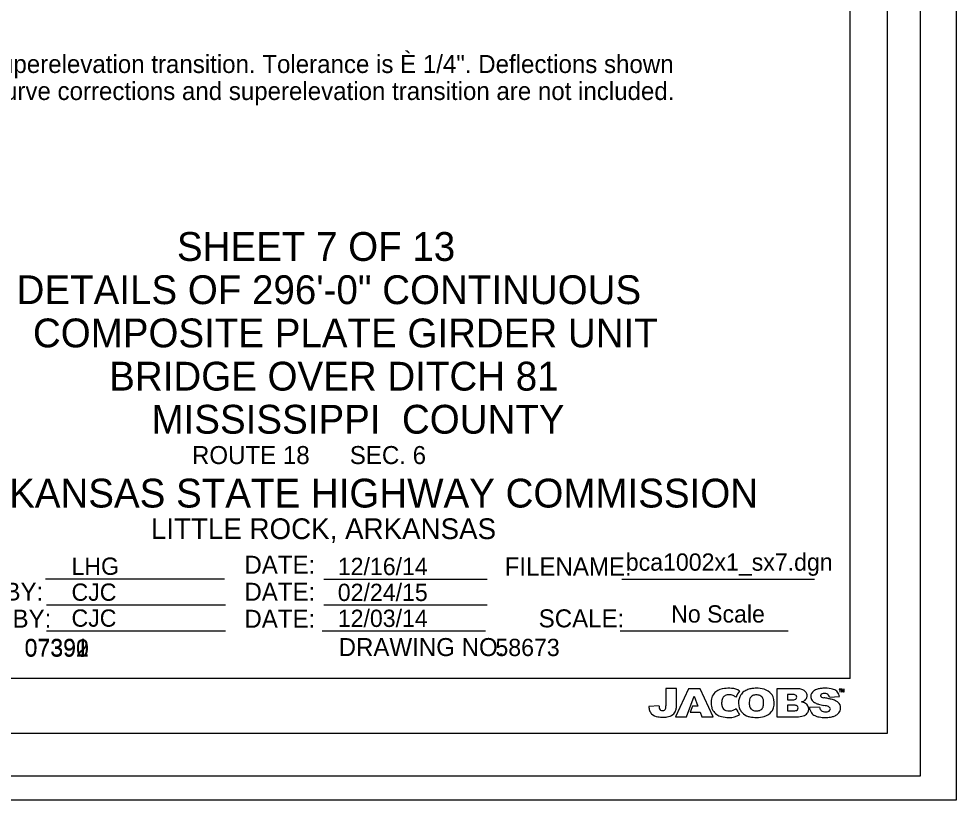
# Model space of a CAD drawing. Extents: x 208.5 to 250.5, y 328.7 to 350.7.
# Drawn here: x 236.52 to 243.03, y 328.74 to 334.16 of the extents above; entities that cross this region are included whole.
import ezdxf

# ---------------------------------------------------------------- set-up
doc = ezdxf.new("R2010")
doc.units = 0
for name, color, linetype in [('border', 7, 'Continuous'), ('Border 2660-Hwy18 - Level 62', 7, 'Continuous'), ('Border 2660-Hwy18 - Level 63', 7, 'Continuous'), ('Border 2660-Hwy18 - Text', 7, 'Continuous'), ('Border 2660-Hwy18 - Title Text', 7, 'Continuous'), ('Bridge No BLFR', 7, 'Continuous'), ('Bridge No BLO', 7, 'Continuous'), ('Bridge No Ditch 81', 7, 'Continuous'), ('Level 40', 7, 'Continuous'), ('Level 62 PDF', 7, 'Continuous'), ('Text', 7, 'Continuous'), ('Title Text', 7, 'Continuous')]:
    doc.layers.add(name, color=color, linetype=linetype)

msp = doc.modelspace()

# ---------------------------------------------------------------- linework, layer by layer
at = {"layer": 'border'}
for p, q in [((242.2907, 329.584), (242.2907, 350.1292)), ((236.7035, 330.2752), (237.9467, 330.2752)), ((238.6367, 330.2741), (239.7707, 330.2741)), ((240.7067, 330.2741), (242.0428, 330.2741)), ((236.7107, 330.0952), (237.9539, 330.0952)), ((238.6367, 330.0941), (239.7707, 330.0941)), ((236.7107, 329.9152), (237.9539, 329.9152)), ((238.6259, 329.9141), (239.7599, 329.9141)), ((240.6943, 329.9141), (241.8599, 329.9141)), ((242.2907, 329.584), (210.2795, 329.584))]:
    msp.add_line(p, q, dxfattribs=at)
for points in [[(241.0855, 329.4044), (241.0855, 329.5145), (241.0114, 329.5145), (241.0114, 329.3938)], [(241.2083, 329.4619), (241.2344, 329.3914), (241.1956, 329.3914), (241.1796, 329.3491), (241.2498, 329.3491), (241.2616, 329.3167), (241.339, 329.3167), (241.2495, 329.5127), (241.1687, 329.5127), (241.0789, 329.3167), (241.1545, 329.3167), (241.2083, 329.4619)], [(241.9247, 329.5127), (241.7825, 329.5127), (241.7825, 329.3167)], [(241.8896, 329.4731), (241.8569, 329.4731), (241.8569, 329.4359)], [(242.2293, 329.5103), (242.2142, 329.5103), (242.2142, 329.5085), (242.2202, 329.5085), (242.2202, 329.4915), (242.2229, 329.4915), (242.2229, 329.5085), (242.2293, 329.5085), (242.2293, 329.5103)], [(242.2338, 329.5073), (242.2338, 329.5073), (242.2399, 329.4915), (242.2417, 329.4915), (242.2477, 329.5073), (242.2477, 329.5073), (242.2477, 329.4915), (242.2502, 329.4915), (242.2502, 329.5103), (242.2468, 329.5103), (242.2408, 329.4946), (242.2347, 329.5103), (242.2314, 329.5103), (242.2314, 329.4915), (242.2338, 329.4915), (242.2338, 329.5073)], [(241.8569, 329.4359), (241.8914, 329.4359)], [(242.1476, 329.4543), (242.2175, 329.4577)], [(240.9639, 329.3929), (240.8931, 329.3893)], [(241.8944, 329.3984), (241.8569, 329.3984), (241.8569, 329.3587)], [(241.8569, 329.3587), (241.895, 329.3587)], [(242.0786, 329.3851), (242.0085, 329.3814)], [(241.7825, 329.3167), (241.9101, 329.3167)]]:
    msp.add_lwpolyline(points, dxfattribs=at)
for centre, radius, start, end in [((241.4075, 329.4273), 0.0809, 126.85134, 155.24445), ((241.4272, 329.401), 0.1137, 94.78534, 126.85134), ((241.448, 329.1527), 0.3629, 86.90301, 94.78534), ((241.4615, 329.4026), 0.1126, 56.9246, 86.90301), ((241.7478, 329.3374), 0.2758, 144.63502, 154.88444), ((241.5953, 329.43), 0.0755, 123.8806, 148.62486), ((241.6324, 329.3747), 0.1421, 111.71043, 123.8806), ((241.6203, 329.4051), 0.1094, 96.53712, 111.71043), ((241.6516, 329.1325), 0.3838, 91.9058, 96.53711), ((241.6458, 329.3501), 0.1661, 73.44767, 92.42532), ((241.6612, 329.4019), 0.1121, 41.1934, 73.44767), ((241.702, 329.4375), 0.0579, 18.69658, 41.1934), ((241.888, 329.3379), 0.1352, 86.2098, 89.3498), ((241.9247, 329.409), 0.1036, 72.18854, 90.1477), ((241.938, 329.4503), 0.0603, 61.48438, 72.18854), ((241.9398, 329.4537), 0.0564, 34.7868, 61.48438), ((241.9603, 329.4679), 0.0315, 16.94547, 34.7868), ((241.9469, 329.4638), 0.0455, 347.09493, 16.94546), ((242.0649, 329.4576), 0.0476, 124.07995, 177.64848), ((242.0961, 329.4116), 0.1032, 108.28083, 124.07995), ((242.0891, 329.4326), 0.0811, 99.81734, 108.28082), ((242.1166, 329.2736), 0.2425, 93.402, 99.81734), ((242.0951, 329.4664), 0.00877, 130.78548, 146.47062), ((242.1061, 329.4537), 0.0256, 97.30547, 130.78548), ((242.1173, 329.2621), 0.2539, 80.65488, 93.40199), ((242.1117, 329.4104), 0.0692, 81.32121, 97.30546), ((242.1167, 329.4434), 0.0359, 57.47403, 81.32121), ((242.1251, 329.4566), 0.0202, 37.19775, 57.47403), ((242.144, 329.4242), 0.0897, 57.59056, 80.65488), ((242.1656, 329.4582), 0.0494, 39.0736, 57.59056), ((242.1564, 329.4508), 0.0612, 6.43854, 39.0736), ((241.4781, 329.4185), 0.1532, 178.6811, 194.39118), ((241.4237, 329.4198), 0.0987, 155.24445, 178.6811), ((241.5022, 329.4122), 0.1037, 161.28337, 178.67021), ((241.4839, 329.4126), 0.0855, 178.67021, 195.85307), ((241.427, 329.4377), 0.0243, 134.3139, 161.28337), ((241.4489, 329.4152), 0.0556, 110.76549, 134.31389), ((241.4479, 329.4177), 0.0529, 91.50728, 110.76549), ((241.4496, 329.3548), 0.1159, 82.6359, 91.50728), ((241.4581, 329.4209), 0.0493, 65.55483, 82.6359), ((241.4294, 329.3577), 0.1187, 54.60016, 65.55482), ((241.6165, 329.4171), 0.1003, 148.62486, 181.28594), ((241.6685, 329.4183), 0.1523, 181.28594, 193.19556), ((241.6817, 329.4145), 0.0917, 160.86113, 181.29811), ((241.6851, 329.4146), 0.0951, 181.29811, 197.94918), ((241.6222, 329.4351), 0.0287, 136.11771, 160.86113), ((241.6389, 329.4191), 0.0518, 117.7176, 136.11771), ((241.6326, 329.4311), 0.0382, 100.21085, 117.7176), ((241.6416, 329.3807), 0.0895, 90.96753, 100.21085), ((241.6406, 329.4079), 0.0622, 67.07702, 90.42176), ((241.6498, 329.4297), 0.0386, 24.62738, 67.07702), ((241.634, 329.4224), 0.056, 2.74416, 24.62738), ((241.5992, 329.4134), 0.091, 342.40029, 0.08449), ((241.4408, 329.4132), 0.2494, 0.08449, 2.74416), ((241.6333, 329.4143), 0.1305, 344.57078, 18.69658), ((241.8913, 329.4992), 0.0633, 270.03631, 284.14376), ((241.8936, 329.4214), 0.0514, 74.87225, 86.2098), ((241.902, 329.4569), 0.0196, 284.14376, 307.88655), ((241.9019, 329.4522), 0.0196, 40.24248, 74.87225), ((241.9049, 329.4531), 0.0149, 307.88655, 341.46246), ((241.9086, 329.4578), 0.0108, 21.96041, 40.24248), ((241.9006, 329.4546), 0.0195, 341.46246, 21.96041), ((241.9344, 329.4939), 0.0753, 284.67851, 296.84115), ((241.9374, 329.3305), 0.092, 61.0815, 79.92424), ((241.9472, 329.4687), 0.0471, 296.84115, 329.81819), ((241.963, 329.3769), 0.039, 44.97734, 61.0815), ((241.9613, 329.4605), 0.0307, 329.81819, 347.09492), ((242.0589, 329.4579), 0.0416, 177.64848, 218.85347), ((242.0706, 329.4673), 0.0566, 218.85347, 233.65492), ((242.0842, 329.4858), 0.0797, 233.65493, 244.76888), ((242.1169, 329.5551), 0.1563, 244.76888, 253.47301), ((242.0936, 329.4644), 0.00815, 165.3108, 208.28871), ((242.1011, 329.4625), 0.016, 146.47062, 165.31079), ((242.1008, 329.4695), 0.0169, 211.74165, 226.63389), ((242.0991, 329.4677), 0.0145, 226.63389, 245.14291), ((242.1161, 329.5044), 0.0549, 245.14291, 260.98065), ((242.0323, 328.9767), 0.4794, 77.5139, 80.98065), ((241.7085, 327.5143), 1.9772, 76.80348, 77.5139), ((242.1133, 329.4476), 0.0351, 11.00509, 37.19775), ((242.1226, 329.2805), 0.1631, 65.69981, 76.80348), ((242.1578, 329.3584), 0.0776, 51.35648, 65.6998), ((242.1736, 329.3782), 0.0523, 36.51625, 51.35648), ((242.1766, 329.3804), 0.0486, 345.16113, 36.51625), ((241.0151, 329.3989), 0.1226, 184.56975, 198.10689), ((240.9486, 329.3771), 0.0527, 198.1069, 225.97986), ((241.0243, 329.3909), 0.0602, 178.25555, 191.49609), ((240.9924, 329.3844), 0.0277, 191.49609, 218.75114), ((240.9836, 329.3773), 0.0164, 218.75114, 257.48803), ((240.9875, 329.395), 0.0345, 257.48804, 275.78339), ((240.9884, 329.3862), 0.0257, 275.78339, 301.69258), ((240.9955, 329.3748), 0.0122, 301.69258, 325.41713), ((240.9821, 329.384), 0.0285, 325.41713, 349.15753), ((240.9323, 329.3936), 0.0792, 349.15753, 360), ((241.0249, 329.3809), 0.0585, 305.86462, 338.78432), ((241.0303, 329.3788), 0.0527, 338.78433, 350.09512), ((240.5413, 329.4642), 0.5492, 350.09512, 351.37058), ((240.9619, 329.4004), 0.1237, 351.37058, 1.82911), ((241.3861, 329.3949), 0.0582, 194.39118, 214.17986), ((241.4429, 329.4335), 0.1268, 214.17986, 231.66155), ((241.4422, 329.4007), 0.0421, 195.85308, 214.53695), ((241.4395, 329.3989), 0.0388, 214.53695, 253.19175), ((241.4505, 329.4353), 0.0769, 253.19175, 291.19559), ((241.4448, 329.4502), 0.0928, 291.19559, 305.51438), ((241.8618, 329.5575), 0.4066, 206.7197, 213.67795), ((241.5867, 329.3991), 0.0683, 193.19556, 217.74992), ((241.6204, 329.4252), 0.1109, 217.74992, 244.17034), ((241.6231, 329.3945), 0.0299, 197.94918, 222.77411), ((241.6359, 329.4063), 0.0474, 222.77411, 250.19554), ((241.637, 329.4094), 0.0507, 250.19554, 269.12639), ((241.6392, 329.5498), 0.1911, 269.12639, 272.0424), ((241.6442, 329.41), 0.0512, 272.0424, 299.54008), ((241.6517, 329.3968), 0.036, 299.54008, 342.40029), ((241.6673, 329.4168), 0.1005, 285.90169, 322.67136), ((241.6918, 329.3982), 0.0698, 322.67136, 344.57078), ((241.8896, 329.1515), 0.2471, 86.68376, 88.87562), ((241.8948, 329.4627), 0.104, 270.00009, 276.67494), ((241.9011, 329.3486), 0.0497, 75.93141, 86.68375), ((241.9019, 329.4022), 0.043, 276.67494, 293.06453), ((241.9052, 329.3649), 0.0328, 59.62021, 75.9314), ((241.9117, 329.379), 0.0178, 293.06453, 337.5037), ((241.9142, 329.3803), 0.015, 30.83409, 59.62021), ((241.9119, 329.379), 0.0177, 337.50371, 30.83409), ((241.953, 329.3742), 0.0511, 313.6357, 342.98447), ((241.9587, 329.3725), 0.0452, 342.98447, 44.97734), ((242.3845, 329.4344), 0.3799, 187.9971, 189.09474), ((242.059, 329.3822), 0.0503, 189.09474, 202.46404), ((242.0939, 329.3967), 0.0881, 202.46404, 215.89258), ((242.0729, 329.3815), 0.0621, 215.89258, 243.29677), ((242.1644, 329.7154), 0.3234, 253.47301, 259.82965), ((242.1303, 329.3929), 0.0523, 188.51407, 201.638), ((242.1113, 329.3853), 0.0319, 201.638, 242.36347), ((242.1174, 329.3969), 0.045, 242.36347, 264.62285), ((242.055, 329.1051), 0.2966, 76.01042, 79.82965), ((242.1207, 329.4324), 0.0806, 264.62285, 273.90099), ((242.123, 329.3982), 0.0464, 273.901, 289.19251), ((242.1031, 329.2984), 0.0974, 67.95933, 76.01043), ((242.1296, 329.3793), 0.0263, 289.19251, 322.56596), ((242.1297, 329.3641), 0.0265, 39.93128, 67.95933), ((242.139, 329.3718), 0.0145, 2.18131, 39.93128), ((242.1394, 329.3718), 0.0141, 322.56597, 2.18131), ((242.1648, 329.3835), 0.0608, 314.02195, 345.16113), ((240.9674, 329.3966), 0.0797, 225.97986, 261.07142), ((240.9929, 329.559), 0.2441, 261.07143, 269.94051), ((240.9929, 329.482), 0.1671, 269.94051, 279.1616), ((241.0046, 329.409), 0.0931, 279.1616, 305.86462), ((241.4117, 329.394), 0.0765, 231.66155, 258.68595), ((241.4551, 329.6112), 0.298, 258.68595, 268.81632), ((241.452, 329.4589), 0.1457, 268.81632, 299.38782), ((241.6095, 329.4027), 0.0859, 244.17034, 259.49425), ((241.6484, 329.6125), 0.2993, 259.49425, 268.64264), ((241.6456, 329.4932), 0.1799, 268.64264, 285.90168), ((241.8999, 329.6546), 0.3381, 271.72242, 279.62791), ((241.9462, 329.3814), 0.0609, 279.62791, 313.6357), ((242.0856, 329.4068), 0.0904, 243.29677, 257.45982), ((242.1122, 329.5263), 0.2128, 257.45982, 268.86561), ((242.1195, 329.8945), 0.5811, 268.86561, 270.76117), ((242.1249, 329.4908), 0.1774, 270.76117, 282.50008), ((242.1397, 329.424), 0.109, 282.50008, 295.61438), ((242.1534, 329.3953), 0.0772, 295.61437, 314.02195)]:
    msp.add_arc(centre, radius, start, end, dxfattribs=at)
at = {"layer": 'Border 2660-Hwy18 - Level 62'}
msp.add_lwpolyline([(208.6594, 350.7149), (242.7778, 350.7149), (242.7778, 328.9054), (208.6594, 328.9054)], close=True, dxfattribs=at)
at = {"layer": 'Border 2660-Hwy18 - Level 63'}
msp.add_lwpolyline([(208.5483, 350.572), (242.5478, 350.572), (242.5478, 329.2025), (208.5483, 329.2025)], close=True, dxfattribs=at)
at = {"layer": 'Level 62 PDF'}
msp.add_lwpolyline([(208.9094, 350.5483), (243.0278, 350.5483), (243.0278, 328.7388), (208.9094, 328.7388)], close=True, dxfattribs=at)

# ---------------------------------------------------------------- texts
at = {"layer": 'Border 2660-Hwy18 - Text'}
for s, p in [('DATE:', (238.0847, 330.3107)), ('FILENAME:', (239.8917, 330.2986)), ('CHECKED BY:', (235.5551, 330.1242)), ('DATE:', (238.0847, 330.1232)), ('DESIGNED BY:', (235.5551, 329.9367)), ('DATE:', (238.0847, 329.9357)), ('SCALE:', (240.1283, 329.9386)), ('DRAWING NO.', (238.739, 329.7393))]:
    msp.add_text(s, height=0.125, dxfattribs=at).set_placement(p)
at = {"layer": 'Border 2660-Hwy18 - Title Text'}
for s, height, p in [('MISSISSIPPI  COUNTY', 0.199999, (237.4397, 331.2831)), ('ROUTE 18      SEC. 6', 0.125, (237.7205, 331.072)), ('ARKANSAS STATE HIGHWAY COMMISSION', 0.199999, (236.0793, 330.7704)), ('LITTLE ROCK, ARKANSAS', 0.144, (237.4355, 330.5512))]:
    msp.add_text(s, height=height, dxfattribs=at).set_placement(p)
at = {"layer": 'Bridge No BLFR'}
msp.add_text('07392', height=0.12, dxfattribs=at).set_placement((236.5584, 329.7347))
at = {"layer": 'Bridge No BLO'}
msp.add_text('07391', height=0.12, dxfattribs=at).set_placement((236.5584, 329.7392))
at = {"layer": 'Bridge No Ditch 81'}
msp.add_text('07390', height=0.12, dxfattribs=at).set_placement((236.5584, 329.7347))
at = {"layer": 'Level 40'}
for s, p in [('Note:  Camber girders for dead load deflection plus vertical curve and superelevation transition. Tolerance is È 1/4". Deflections shown', (231.1199, 333.7863)), ('are from a chord extending from C.L. Bearing to C.L. Bearing. Vertical curve corrections and superelevation transition are not included.', (231.1199, 333.5988))]:
    msp.add_text(s, height=0.1249998, dxfattribs=at).set_placement(p)
at = {"layer": 'Text'}
for s, p in [('bca1002x1_sx7.dgn', (240.7331, 330.3319)), ('LHG', (236.8841, 330.3031)), ('12/16/14', (238.7332, 330.3015)), ('CJC', (236.8841, 330.1231)), ('02/24/15', (238.7332, 330.1215)), ('CJC', (236.8841, 329.9431)), ('12/03/14', (238.7332, 329.9415)), ('No Scale', (241.0481, 329.9719)), ('58673', (239.8279, 329.7394))]:
    msp.add_text(s, height=0.12, dxfattribs=at).set_placement(p)
at = {"layer": 'Title Text'}
for s, p in [('SHEET 7 OF 13', (237.6164, 332.4821)), ('DETAILS OF 296\'-0" CONTINUOUS', (236.5029, 332.1821)), ('COMPOSITE PLATE GIRDER UNIT', (236.6162, 331.8821)), ('BRIDGE OVER DITCH 81', (237.1458, 331.5821))]:
    msp.add_text(s, height=0.199999, dxfattribs=at).set_placement(p)

doc.saveas('drawing.dxf')
